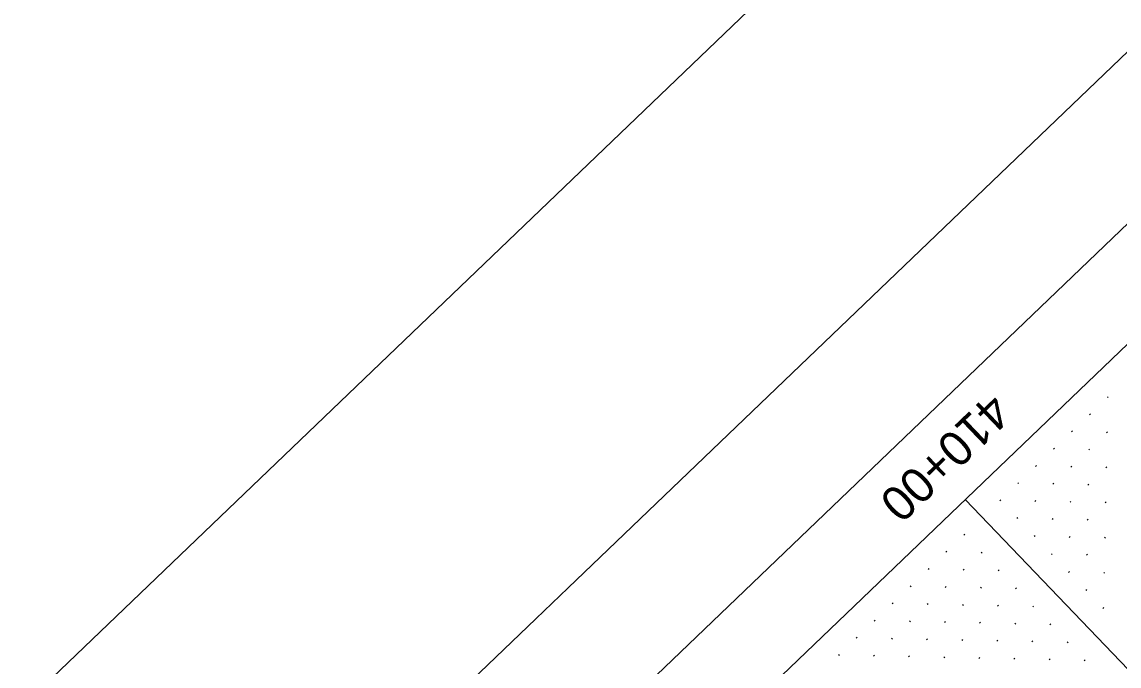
# Model space of a CAD drawing. Extents: x 2148987 to 2151117, y 142806 to 144993.
# Drawn here: x 2149649.5 to 2149870.3, y 144315 to 144444.6 of the extents above; entities that cross this region are included whole.
import ezdxf

# ---------------------------------------------------------------- set-up
doc = ezdxf.new("R2010")
doc.units = 0
for name, color, linetype in [('BASELINE', 7, 'Continuous'), ('PR_ABUT_PH3', 7, 'Continuous'), ('PR_PIER_PH3', 7, 'Continuous'), ('PR_Road_Concrete', 7, 'Continuous'), ('SHT_Profile_Grid_Minor', 7, 'Continuous'), ('Wall D Bore Txt', 7, 'Continuous')]:
    doc.layers.add(name, color=color, linetype=linetype)

msp = doc.modelspace()

# ---------------------------------------------------------------- linework, layer by layer
at = {"layer": 'BASELINE'}
msp.add_lwpolyline([(2151029.45, 144024.32), (2149802.07, 142848.08), (2149040.98, 143642.27), (2150268.36, 144818.51)], close=True, dxfattribs=at)
at = {"layer": 'PR_ABUT_PH3'}
msp.add_lwpolyline([(2151117.11, 144051.19), (2149817.52, 142805.76), (2148987.24, 143672.15), (2150286.82, 144917.58)], close=True, dxfattribs=at)
at = {"layer": 'PR_PIER_PH3'}
msp.add_line((2149839.3, 144348.47), (2150161.04, 144012.74), dxfattribs=at)
at = {"layer": 'PR_Road_Concrete'}
msp.add_line((2150227.37, 144720.36), (2149279.76, 143812.24), dxfattribs=at)
msp.add_lwpolyline([(2150941.76, 143974.91), (2149804.63, 142885.16), (2149078.13, 143643.25), (2150215.26, 144733)], close=True, dxfattribs=at)
at = {"layer": 'SHT_Profile_Grid_Minor'}
for p, q in [((2149868.12, 144369.16), (2149867.94, 144368.99)), ((2149864.51, 144365.7), (2149864.33, 144365.53)), ((2149860.9, 144362.24), (2149860.72, 144362.07)), ((2149867.97, 144362.09), (2149867.79, 144361.92)), ((2149857.29, 144358.78), (2149857.11, 144358.61)), ((2149864.36, 144358.63), (2149864.18, 144358.46)), ((2149853.68, 144355.32), (2149853.5, 144355.15)), ((2149860.75, 144355.17), (2149860.57, 144355)), ((2149867.82, 144355.02), (2149867.64, 144354.85)), ((2149850.07, 144351.86), (2149849.89, 144351.69)), ((2149857.14, 144351.71), (2149856.96, 144351.54)), ((2149864.21, 144351.56), (2149864.03, 144351.39)), ((2149846.46, 144348.4), (2149846.28, 144348.23)), ((2149853.53, 144348.25), (2149853.35, 144348.08)), ((2149860.6, 144348.1), (2149860.42, 144347.93)), ((2149867.67, 144347.95), (2149867.49, 144347.78)), ((2149849.92, 144344.79), (2149849.74, 144344.62)), ((2149856.99, 144344.64), (2149856.81, 144344.47)), ((2149864.06, 144344.49), (2149863.88, 144344.32)), ((2149839.24, 144341.48), (2149839.06, 144341.31)), ((2149853.38, 144341.18), (2149853.2, 144341.01)), ((2149860.45, 144341.03), (2149860.27, 144340.86)), ((2149867.52, 144340.88), (2149867.34, 144340.71)), ((2149835.63, 144338.02), (2149835.45, 144337.85)), ((2149842.7, 144337.87), (2149842.52, 144337.7)), ((2149856.84, 144337.57), (2149856.66, 144337.4)), ((2149863.91, 144337.42), (2149863.73, 144337.25)), ((2149832.02, 144334.56), (2149831.84, 144334.39)), ((2149839.09, 144334.41), (2149838.91, 144334.24)), ((2149846.16, 144334.26), (2149845.98, 144334.09)), ((2149860.3, 144333.96), (2149860.12, 144333.79)), ((2149867.37, 144333.81), (2149867.19, 144333.64)), ((2149828.41, 144331.1), (2149828.23, 144330.93)), ((2149835.48, 144330.95), (2149835.3, 144330.78)), ((2149842.55, 144330.8), (2149842.37, 144330.63)), ((2149849.62, 144330.65), (2149849.44, 144330.48)), ((2149863.76, 144330.35), (2149863.58, 144330.18)), ((2149824.8, 144327.64), (2149824.62, 144327.47)), ((2149831.87, 144327.49), (2149831.69, 144327.32)), ((2149838.94, 144327.34), (2149838.76, 144327.17)), ((2149846.01, 144327.19), (2149845.83, 144327.02)), ((2149853.08, 144327.04), (2149852.9, 144326.87)), ((2149867.22, 144326.74), (2149867.04, 144326.57)), ((2149821.19, 144324.19), (2149821.01, 144324.01)), ((2149828.26, 144324.03), (2149828.08, 144323.86)), ((2149835.33, 144323.88), (2149835.15, 144323.71)), ((2149842.4, 144323.73), (2149842.22, 144323.56)), ((2149849.47, 144323.58), (2149849.29, 144323.41)), ((2149856.54, 144323.43), (2149856.36, 144323.26)), ((2149817.58, 144320.73), (2149817.4, 144320.55)), ((2149824.65, 144320.58), (2149824.47, 144320.4)), ((2149831.72, 144320.42), (2149831.54, 144320.25)), ((2149838.79, 144320.27), (2149838.61, 144320.1)), ((2149845.86, 144320.12), (2149845.68, 144319.95)), ((2149852.93, 144319.97), (2149852.75, 144319.8)), ((2149860, 144319.82), (2149859.82, 144319.65)), ((2149813.97, 144317.27), (2149813.79, 144317.09)), ((2149821.04, 144317.12), (2149820.86, 144316.94)), ((2149828.11, 144316.97), (2149827.93, 144316.79)), ((2149835.18, 144316.81), (2149835, 144316.64)), ((2149842.25, 144316.66), (2149842.07, 144316.49)), ((2149849.32, 144316.51), (2149849.14, 144316.34)), ((2149856.39, 144316.36), (2149856.21, 144316.19)), ((2149863.46, 144316.21), (2149863.28, 144316.04))]:
    msp.add_line(p, q, dxfattribs=at)

# ---------------------------------------------------------------- texts
at = {"layer": 'Wall D Bore Txt'}
msp.add_text('410+00', height=7, rotation=223.7809, dxfattribs=at).set_placement((2149844.37, 144370.29))

doc.saveas('drawing.dxf')
